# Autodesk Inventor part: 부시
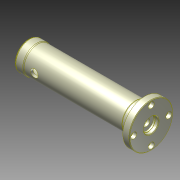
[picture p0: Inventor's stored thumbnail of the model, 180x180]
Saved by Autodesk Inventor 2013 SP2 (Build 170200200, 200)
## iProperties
Created: 2024-07
Part Number: 부시
Material: Generic
Document SubType Name: Modeling
Designer: 601
Density: 1 g/cm^3
Author: 601
변환 표준: STEP AP214IS
전처리기: Build: 200, Release: 2013 SP2 Update 6 - Date: Thu 07/17/2014
전송 단위: 밀리미터
불확실성: 0.01
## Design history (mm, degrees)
node "부시1"
node "솔리드1"
node "기준1"
